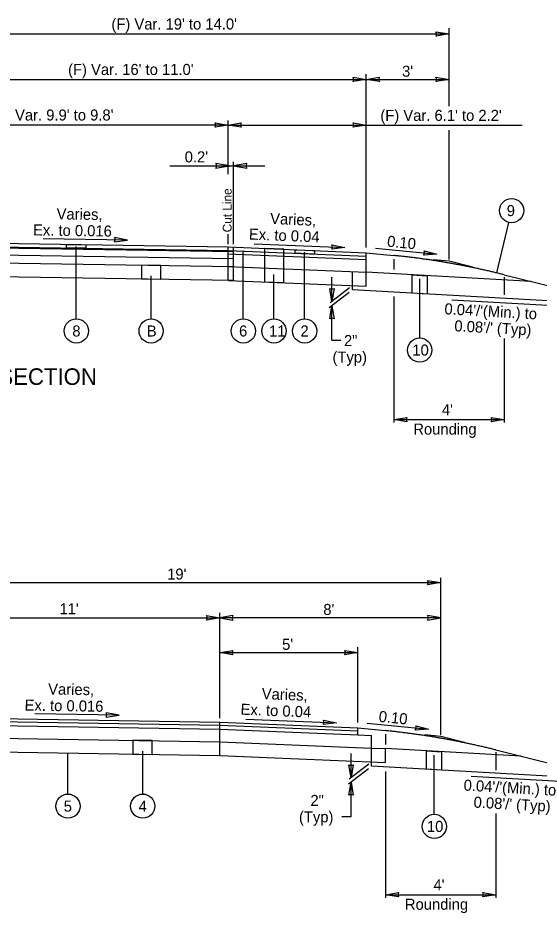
# Model space of a CAD drawing. Extents: x -219 to 803, y -225 to 180.
# Drawn here: x 90.5 to 128.3, y 22.4 to 87.3 of the extents above; entities that cross this region are included whole.
import ezdxf

# ---------------------------------------------------------------- set-up
doc = ezdxf.new("R2010")
doc.units = 0
for name, color, linetype in [('Level 16', 7, 'Continuous'), ('SH_Data', 7, 'Continuous'), ('XS_X_Pavt', 7, 'Continuous')]:
    doc.layers.add(name, color=color, linetype=linetype)

msp = doc.modelspace()

# ---------------------------------------------------------------- linework, layer by layer
at = {"layer": 'Level 16'}
for p, q in [((120.8, 86.286), (121.75, 86.128)), ((121.75, 80.906), (121.75, 86.556)), ((83.75, 86.128), (121.75, 86.128)), ((121.75, 86.128), (120.803, 85.97)), ((120.803, 85.97), (120.803, 85.97)), ((115.75, 70.662), (115.75, 83.209)), ((83.75, 82.828), (115.75, 82.828)), ((114.8, 82.986), (115.75, 82.828)), ((115.75, 82.828), (114.803, 82.67)), ((114.803, 82.67), (114.803, 82.67)), ((115.75, 82.828), (116.696, 82.986)), ((116.7, 82.67), (115.75, 82.828)), ((115.75, 82.828), (121.75, 82.828)), ((116.696, 82.986), (116.696, 82.986)), ((120.8, 82.986), (121.75, 82.828)), ((121.75, 82.828), (120.803, 82.67)), ((120.803, 82.67), (120.803, 82.67)), ((105.75, 75.964), (105.75, 79.846)), ((105.75, 79.528), (83.75, 79.528)), ((104.8, 79.686), (105.75, 79.528)), ((105.75, 79.528), (104.803, 79.37)), ((104.803, 79.37), (104.803, 79.37)), ((105.75, 79.528), (106.696, 79.686)), ((106.7, 79.37), (105.75, 79.528)), ((105.75, 79.528), (115.75, 79.528)), ((106.696, 79.686), (106.696, 79.686)), ((114.8, 79.686), (115.75, 79.528)), ((115.75, 79.528), (114.803, 79.37)), ((114.803, 79.37), (114.803, 79.37)), ((115.75, 79.528), (127.042, 79.528)), ((121.75, 69.775), (121.75, 79.157)), ((101.527, 76.573), (105.817, 76.573)), ((104.867, 76.415), (105.817, 76.573)), ((105.817, 76.573), (104.871, 76.731)), ((104.871, 76.731), (104.871, 76.731)), ((105.817, 76.573), (106.15, 76.573)), ((106.15, 70.892), (106.15, 76.86)), ((107.1, 76.731), (106.15, 76.573)), ((106.15, 76.573), (107.097, 76.415)), ((106.15, 76.573), (108.396, 76.573)), ((107.097, 76.415), (107.097, 76.415)), ((125.196, 68.814), (126.074, 72.477)), ((98.47, 71.195), (97.528, 71.375)), ((97.528, 71.375), (97.528, 71.375)), ((105.75, 70.904), (105.75, 71.625)), ((83.749, 70.793), (105.749, 70.445)), ((83.75, 71.043), (105.75, 70.694)), ((98.47, 71.195), (92.358, 71.293)), ((94.757, 65.483), (94.757, 70.719)), ((97.517, 71.06), (98.47, 71.195)), ((105.75, 70.694), (115.75, 70.278)), ((105.75, 70.445), (105.75, 70.694)), ((107.643, 70.921), (114.201, 70.648)), ((113.258, 70.845), (114.201, 70.648)), ((105.748, 70.445), (115.748, 70.028)), ((105.75, 68.278), (105.75, 70.445)), ((105.754, 70.194), (115.75, 69.778)), ((106.85, 65.483), (106.85, 70.399)), ((109.793, 68.109), (109.793, 70.526)), ((111.29, 65.483), (111.29, 70.325)), ((114.201, 70.648), (113.248, 70.529)), ((113.248, 70.529), (113.248, 70.529)), ((115.75, 69.778), (115.75, 70.278)), ((115.75, 70.278), (117.75, 70.078)), ((116.43, 70.618), (120.871, 70.173)), ((120.871, 70.173), (119.914, 70.11)), ((119.914, 70.11), (119.914, 70.11)), ((119.942, 70.425), (120.871, 70.173)), ((115.75, 68.861), (115.75, 69.778)), ((117.75, 69.822), (117.75, 69.071)), ((120.6, 69.793), (121.75, 69.678)), ((121.75, 69.678), (123.479, 69.246)), ((100.867, 68.355), (100.867, 69.355)), ((105.76, 69.277), (115.75, 68.861)), ((114.75, 67.903), (114.75, 68.903)), ((115.75, 67.861), (115.75, 68.861)), ((127.691, 68.193), (115.75, 68.861)), ((99.467, 68.377), (100.867, 68.355)), ((100.175, 65.483), (100.175, 68.593)), ((105.765, 68.277), (115.75, 67.861)), ((108.393, 68.168), (109.793, 68.109)), ((109.07, 65.483), (109.07, 68.696)), ((113.261, 66.747), (113.261, 68.509)), ((119.623, 64.1), (119.623, 68.377)), ((125.75, 68.678), (139.943, 65.13)), ((125.75, 68.509), (125.75, 67.216)), ((113.261, 66.747), (113.103, 67.693)), ((113.103, 67.693), (113.103, 67.693)), ((114.537, 67.738), (113.132, 66.647)), ((113.419, 67.697), (113.261, 66.747)), ((114.75, 67.582), (114.75, 67.916)), ((134.575, 66.472), (114.75, 67.582)), ((114.524, 67.407), (113.075, 66.281)), ((117.75, 67.107), (117.75, 57.975)), ((121.952, 66.861), (129.828, 66.42)), ((113.103, 65.476), (113.261, 66.426)), ((113.261, 63.953), (113.261, 66.426)), ((113.261, 66.426), (113.419, 65.479)), ((113.419, 65.479), (113.419, 65.479)), ((113.261, 63.953), (113.92, 63.953)), ((125.75, 64.071), (125.75, 57.975)), ((117.75, 58.193), (118.697, 58.351)), ((118.7, 58.035), (117.75, 58.193)), ((117.75, 58.193), (125.75, 58.193)), ((118.697, 58.351), (118.697, 58.351)), ((124.8, 58.351), (125.75, 58.193)), ((125.75, 58.193), (124.803, 58.035)), ((124.803, 58.035), (124.803, 58.035)), ((121.141, 35.351), (121.141, 46.722)), ((83.141, 46.382), (121.141, 46.382)), ((120.191, 46.54), (121.141, 46.382)), ((121.141, 46.382), (120.194, 46.224)), ((120.194, 46.224), (120.194, 46.224)), ((105.141, 36.551), (105.141, 44.194)), ((83.141, 43.827), (105.141, 43.827)), ((104.191, 43.985), (105.141, 43.827)), ((105.141, 43.827), (104.194, 43.669)), ((104.194, 43.669), (104.194, 43.669)), ((106.091, 43.985), (105.141, 43.827)), ((121.141, 43.827), (105.141, 43.827)), ((105.141, 43.827), (106.088, 43.669)), ((106.088, 43.669), (106.088, 43.669)), ((120.191, 43.669), (121.141, 43.827)), ((121.141, 43.827), (120.194, 43.985)), ((120.194, 43.985), (120.194, 43.985)), ((115.141, 36.237), (115.141, 41.698)), ((105.141, 41.305), (106.087, 41.463)), ((106.09, 41.147), (105.141, 41.305)), ((105.141, 41.305), (115.141, 41.305)), ((106.087, 41.463), (106.087, 41.463)), ((114.191, 41.463), (115.141, 41.305)), ((115.141, 41.305), (114.194, 41.147)), ((114.194, 41.147), (114.194, 41.147)), ((83.141, 36.619), (105.141, 36.27)), ((83.141, 36.41), (105.141, 36.062)), ((97.861, 36.771), (91.749, 36.868)), ((96.908, 36.635), (97.861, 36.771)), ((97.861, 36.771), (96.919, 36.951)), ((96.919, 36.951), (96.919, 36.951)), ((107.034, 36.497), (113.592, 36.224)), ((112.649, 36.421), (113.592, 36.224)), ((83.141, 36.119), (105.145, 35.77)), ((105.141, 36.27), (115.141, 35.854)), ((105.141, 33.854), (105.141, 36.27)), ((105.141, 33.822), (105.141, 36.239)), ((105.141, 36.062), (115.141, 35.645)), ((105.145, 35.77), (115.141, 35.354)), ((113.592, 36.224), (112.639, 36.105)), ((112.639, 36.105), (112.639, 36.105)), ((115.141, 35.354), (115.141, 35.854)), ((115.141, 35.854), (117.141, 35.654)), ((115.821, 36.193), (120.262, 35.749)), ((120.262, 35.749), (119.304, 35.686)), ((119.304, 35.686), (119.304, 35.686)), ((119.333, 36.001), (120.262, 35.749)), ((83.141, 35.202), (105.151, 34.853)), ((115.141, 35.354), (116.141, 35.312)), ((116.141, 34.396), (116.141, 35.312)), ((117.141, 35.397), (117.141, 34.647)), ((119.991, 35.369), (121.141, 35.254)), ((121.141, 35.254), (122.87, 34.822)), ((100.258, 33.931), (100.258, 34.931)), ((105.151, 34.853), (116.141, 34.396)), ((116.141, 34.396), (117.141, 34.354)), ((116.141, 33.396), (116.141, 34.396)), ((83.141, 34.202), (105.155, 33.853)), ((94.148, 31.059), (94.148, 34.027)), ((98.858, 33.953), (100.258, 33.931)), ((99.566, 31.059), (99.566, 34.169)), ((105.155, 33.853), (117.141, 33.354)), ((114.652, 32.24), (114.652, 34.002)), ((117.141, 33.354), (117.141, 34.354)), ((126.934, 33.806), (117.141, 34.354)), ((120.68, 29.593), (120.68, 33.87)), ((125.141, 34.254), (139.334, 30.706)), ((125.141, 34.085), (125.141, 32.791)), ((114.652, 32.24), (114.494, 33.186)), ((114.494, 33.186), (114.494, 33.186)), ((115.928, 33.23), (114.522, 32.139)), ((114.81, 33.189), (114.652, 32.24)), ((116.141, 33.074), (116.141, 33.408)), ((115.915, 32.899), (114.466, 31.774)), ((133.818, 32.085), (116.141, 33.074)), ((117.141, 32.683), (117.141, 23.551)), ((114.494, 30.969), (114.652, 31.918)), ((114.652, 29.446), (114.652, 31.918)), ((114.652, 31.918), (114.81, 30.972)), ((123.343, 32.354), (131.219, 31.912)), ((114.81, 30.972), (114.81, 30.972)), ((113.993, 29.446), (114.652, 29.446)), ((125.141, 29.647), (125.141, 23.551)), ((117.141, 23.769), (118.088, 23.927)), ((118.091, 23.611), (117.141, 23.769)), ((117.141, 23.769), (125.141, 23.769)), ((118.088, 23.927), (118.088, 23.927)), ((124.191, 23.927), (125.141, 23.769)), ((125.141, 23.769), (124.194, 23.611)), ((124.194, 23.611), (124.194, 23.611))]:
    msp.add_line(p, q, dxfattribs=at)
for points in [[(94.052, 70.88), (95.452, 70.858), (95.452, 70.608), (94.052, 70.63)], [(110.616, 70.492), (112.016, 70.433), (112.016, 70.184), (110.616, 70.242)], [(119.065, 68.676), (120.154, 68.615), (120.154, 67.279), (119.065, 67.34)], [(120.115, 34.187), (121.204, 34.126), (121.204, 32.791), (120.115, 32.852)]]:
    msp.add_lwpolyline(points, close=True, dxfattribs=at)
for points in [[(109.793, 70.526), (108.393, 70.584), (108.393, 68.168)], [(100.867, 69.355), (99.467, 69.377), (99.467, 68.377)], [(100.258, 34.931), (98.858, 34.953), (98.858, 33.953)]]:
    msp.add_lwpolyline(points, dxfattribs=at)
for centre in [(126.278, 73.328), (94.757, 64.608), (100.175, 64.608), (106.85, 64.608), (109.07, 64.608), (111.29, 64.608), (119.623, 63.225), (94.148, 30.184), (99.566, 30.184), (120.68, 28.718)]:
    msp.add_circle(centre, 0.875, dxfattribs=at)
for centre, start, end in [((120.561, 86.126), 327.14123, 33.822), ((114.561, 82.826), 327.14123, 33.822), ((116.939, 82.83), 147.14123, 213.822), ((120.561, 82.826), 327.14123, 33.822), ((104.561, 79.526), 327.14123, 33.822), ((106.939, 79.53), 147.14123, 213.822), ((114.561, 79.526), 327.14123, 33.822), ((104.628, 76.575), 326.178, 32.85877), ((107.339, 76.571), 146.178, 212.85877), ((97.282, 71.225), 324.80397, 31.48474), ((113.013, 70.695), 324.75531, 31.43608), ((119.688, 70.29), 321.43103, 28.1118), ((113.259, 67.936), 237.14123, 303.822), ((113.263, 65.237), 57.14123, 123.822), ((118.939, 58.195), 147.14123, 213.822), ((124.561, 58.191), 327.14123, 33.822), ((119.952, 46.38), 327.14123, 33.822), ((103.952, 43.825), 327.14123, 33.822), ((106.33, 43.825), 146.178, 212.85877), ((119.952, 43.829), 326.178, 32.85877), ((106.329, 41.307), 147.14123, 213.822), ((113.952, 41.303), 327.14123, 33.822), ((96.673, 36.801), 324.80397, 31.48474), ((112.404, 36.271), 324.75531, 31.43608), ((119.079, 35.866), 321.43103, 28.1118), ((114.65, 33.428), 237.14123, 303.822), ((114.654, 30.73), 57.14123, 123.822), ((118.33, 23.771), 147.14123, 213.822), ((123.952, 23.767), 327.14123, 33.822)]:
    msp.add_arc(centre, 0.288, start, end, dxfattribs=at)
for points in [[(125.75, 68.678), (125.596, 68.716), (125.442, 68.754), (125.288, 68.791), (125.135, 68.828), (124.981, 68.865), (124.827, 68.901), (124.673, 68.936), (124.519, 68.971), (124.365, 69.006), (124.212, 69.04), (124.058, 69.074), (123.904, 69.108), (123.75, 69.14), (123.596, 69.173), (123.442, 69.205), (123.288, 69.237), (123.135, 69.268), (122.981, 69.298), (122.827, 69.329), (122.673, 69.358), (122.519, 69.388), (122.365, 69.417), (122.212, 69.445), (122.058, 69.473), (121.904, 69.501), (121.75, 69.528), (121.596, 69.555), (121.442, 69.581), (121.288, 69.607), (121.135, 69.632), (120.981, 69.657), (120.827, 69.682), (120.673, 69.706), (120.519, 69.729), (120.365, 69.752), (120.212, 69.775), (120.058, 69.797), (119.904, 69.819), (119.75, 69.84), (119.596, 69.861), (119.442, 69.882), (119.288, 69.902), (119.135, 69.922), (118.981, 69.941), (118.827, 69.959), (118.673, 69.978), (118.519, 69.995), (118.365, 70.013), (118.212, 70.03), (118.058, 70.046), (117.904, 70.062), (117.75, 70.078)], [(125.141, 34.254), (124.987, 34.292), (124.833, 34.33), (124.679, 34.367), (124.525, 34.404), (124.372, 34.441), (124.218, 34.477), (124.064, 34.512), (123.91, 34.547), (123.756, 34.582), (123.602, 34.616), (123.449, 34.65), (123.295, 34.683), (123.141, 34.716), (122.987, 34.749), (122.833, 34.781), (122.679, 34.812), (122.525, 34.844), (122.372, 34.874), (122.218, 34.905), (122.064, 34.934), (121.91, 34.964), (121.756, 34.993), (121.602, 35.021), (121.449, 35.049), (121.295, 35.077), (121.141, 35.104), (120.987, 35.131), (120.833, 35.157), (120.679, 35.183), (120.525, 35.208), (120.372, 35.233), (120.218, 35.257), (120.064, 35.281), (119.91, 35.305), (119.756, 35.328), (119.602, 35.351), (119.449, 35.373), (119.295, 35.395), (119.141, 35.416), (118.987, 35.437), (118.833, 35.458), (118.679, 35.478), (118.525, 35.497), (118.372, 35.517), (118.218, 35.535), (118.064, 35.554), (117.91, 35.571), (117.756, 35.589), (117.602, 35.606), (117.449, 35.622), (117.295, 35.638), (117.141, 35.654)]]:
    msp.add_spline(points, degree=3, dxfattribs=at)
at = {"layer": 'SH_Data'}
for p, q in [((83.783, 70.709), (106.15, 70.355)), ((83.75, 70.209), (106.15, 69.855)), ((106.15, 68.278), (106.15, 70.678)), ((83.75, 69.627), (106.15, 69.272)), ((83.75, 68.632), (106.15, 68.278))]:
    msp.add_line(p, q, dxfattribs=at)
at = {"layer": 'XS_X_Pavt'}
for points in [[(121.743, 86.129), (121.747, 86.127)], [(121.745, 86.13), (121.747, 86.127)], [(115.743, 82.829), (115.747, 82.827)], [(115.745, 82.83), (115.747, 82.827)], [(115.755, 82.826), (115.752, 82.828)], [(115.757, 82.826), (115.753, 82.828)], [(121.743, 82.829), (121.747, 82.827)], [(121.745, 82.83), (121.747, 82.827)], [(105.743, 79.529), (105.747, 79.527)], [(105.745, 79.53), (105.747, 79.527)], [(105.755, 79.526), (105.752, 79.528)], [(105.757, 79.526), (105.753, 79.528)], [(115.743, 79.529), (115.747, 79.527)], [(115.745, 79.53), (115.747, 79.527)], [(105.81, 76.572), (105.814, 76.573)], [(105.812, 76.571), (105.815, 76.573)], [(106.155, 76.575), (106.153, 76.572)], [(106.157, 76.574), (106.153, 76.572)], [(98.463, 71.194), (98.467, 71.196)], [(98.465, 71.193), (98.468, 71.196)], [(114.194, 70.649), (114.198, 70.647)], [(114.196, 70.65), (114.198, 70.647)], [(120.864, 70.175), (120.868, 70.173)], [(120.866, 70.176), (120.869, 70.173)], [(113.259, 66.421), (113.262, 66.423)], [(113.262, 66.754), (113.26, 66.75)], [(113.263, 66.752), (113.26, 66.749)], [(113.26, 66.419), (113.262, 66.423)], [(117.755, 58.191), (117.753, 58.194)], [(117.757, 58.192), (117.753, 58.194)], [(125.743, 58.195), (125.747, 58.193)], [(125.745, 58.195), (125.747, 58.193)], [(121.134, 46.383), (121.138, 46.381)], [(121.136, 46.384), (121.138, 46.381)], [(105.134, 43.828), (105.138, 43.826)], [(105.136, 43.829), (105.138, 43.826)], [(105.146, 43.829), (105.144, 43.826)], [(105.148, 43.828), (105.144, 43.826)], [(121.134, 43.825), (121.138, 43.827)], [(121.136, 43.825), (121.138, 43.827)], [(105.146, 41.303), (105.143, 41.306)], [(105.148, 41.304), (105.144, 41.306)], [(115.134, 41.307), (115.138, 41.305)], [(115.136, 41.307), (115.138, 41.305)], [(97.854, 36.77), (97.858, 36.772)], [(97.856, 36.769), (97.859, 36.771)], [(113.585, 36.225), (113.588, 36.223)], [(113.586, 36.226), (113.589, 36.223)], [(120.255, 35.751), (120.259, 35.749)], [(120.257, 35.752), (120.259, 35.749)], [(114.65, 31.913), (114.653, 31.916)], [(114.653, 32.247), (114.651, 32.243)], [(114.654, 32.245), (114.651, 32.242)], [(114.651, 31.912), (114.653, 31.915)], [(117.146, 23.767), (117.144, 23.77)], [(117.148, 23.768), (117.144, 23.77)], [(125.134, 23.77), (125.138, 23.769)], [(125.136, 23.771), (125.138, 23.769)]]:
    msp.add_lwpolyline(points, dxfattribs=at)

# ---------------------------------------------------------------- texts
at = {"layer": 'Level 16'}
for s, height, p in [("(F) Var. 19' to 14.0'", 0.8, (97.298, 86.447)), ("(F) Var. 16' to 11.0'", 0.8, (94.159, 83.155)), ("3'", 0.8, (118.344, 83.028)), ("(F) Var. 9.9' to 9.8'", 0.8, (88.655, 79.855)), ("(F) Var. 6.1' to 2.2'", 0.8, (116.773, 79.829)), ("0.2'", 0.8, (102.604, 76.821)), ('9', 0.8, (125.925, 72.928)), ('8', 0.8, (94.468, 64.208)), ('B', 0.8, (99.863, 64.208)), ('6', 0.8, (106.541, 64.208)), ('11', 0.8, (108.715, 64.208)), ('2', 0.8, (110.991, 64.208)), ('2"', 0.8, (114.137, 63.51)), ('10', 0.8, (119.091, 62.825)), ('(Typ)', 0.8, (113.308, 62.32)), ('PAVEMENT WIDENING - NORMAL SECTION', 1.2, (62.901, 60.702)), ("4'", 0.8, (121.225, 58.501)), ('Rounding', 0.8, (119.159, 57.101)), ("19'", 0.8, (101.334, 46.598)), ("11'", 0.8, (93.537, 44.079)), ("8'", 0.8, (112.641, 44.032)), ("5'", 0.8, (109.659, 41.506)), ('5', 0.8, (93.843, 29.784)), ('4', 0.8, (99.27, 29.784)), ('2"', 0.8, (111.707, 30.199)), ('(Typ)', 0.8, (110.879, 29.008)), ('10', 0.8, (120.148, 28.318)), ("4'", 0.8, (120.616, 24.077)), ('Rounding', 0.8, (118.55, 22.677))]:
    msp.add_text(s, height=height, dxfattribs=at).set_placement(p)
for s, height, rotation, p in [('Cut Line', 0.64, 90, (106.005, 71.754)), ('Varies,', 0.8, 359.08305, (93.322, 72.697)), ('Varies,', 0.8, 357.61408, (108.779, 72.364)), ('Ex. to 0.016', 0.8, 359.08305, (91.615, 71.534)), ('Ex. to 0.04', 0.8, 357.61408, (107.244, 71.237)), ('0.10', 0.8, 354.2898, (117.235, 70.724)), ("0.04'/'(Min.) to", 0.8, 356.79433, (121.397, 65.824)), ("0.08'/' (Typ)", 0.8, 356.79433, (122.116, 64.591)), ('Varies,', 0.8, 359.08305, (92.713, 38.273)), ('Varies,', 0.8, 357.61408, (108.17, 37.94)), ('Ex. to 0.016', 0.8, 359.08305, (91.006, 37.109)), ('Ex. to 0.04', 0.8, 357.61408, (106.635, 36.813)), ('0.10', 0.8, 354.2898, (116.626, 36.3)), ("0.04'/'(Min.) to", 0.8, 356.79433, (122.787, 31.316)), ("0.08'/' (Typ)", 0.8, 356.79433, (123.507, 30.084))]:
    msp.add_text(s, height=height, rotation=rotation, dxfattribs=at).set_placement(p)

doc.saveas('drawing.dxf')
